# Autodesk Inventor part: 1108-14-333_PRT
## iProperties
Created: 2007-03
Part Number: 1108-14-333_PRT
Document SubType Name: Modeling
Designer: Andy Moles
Density: 1 g/cm^3
Mass: 0.443583 g
Surface Area: 6.97725 cm^2
Volume: 0.443583 cm^3
Author: Andy Moles
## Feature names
1. Base1
